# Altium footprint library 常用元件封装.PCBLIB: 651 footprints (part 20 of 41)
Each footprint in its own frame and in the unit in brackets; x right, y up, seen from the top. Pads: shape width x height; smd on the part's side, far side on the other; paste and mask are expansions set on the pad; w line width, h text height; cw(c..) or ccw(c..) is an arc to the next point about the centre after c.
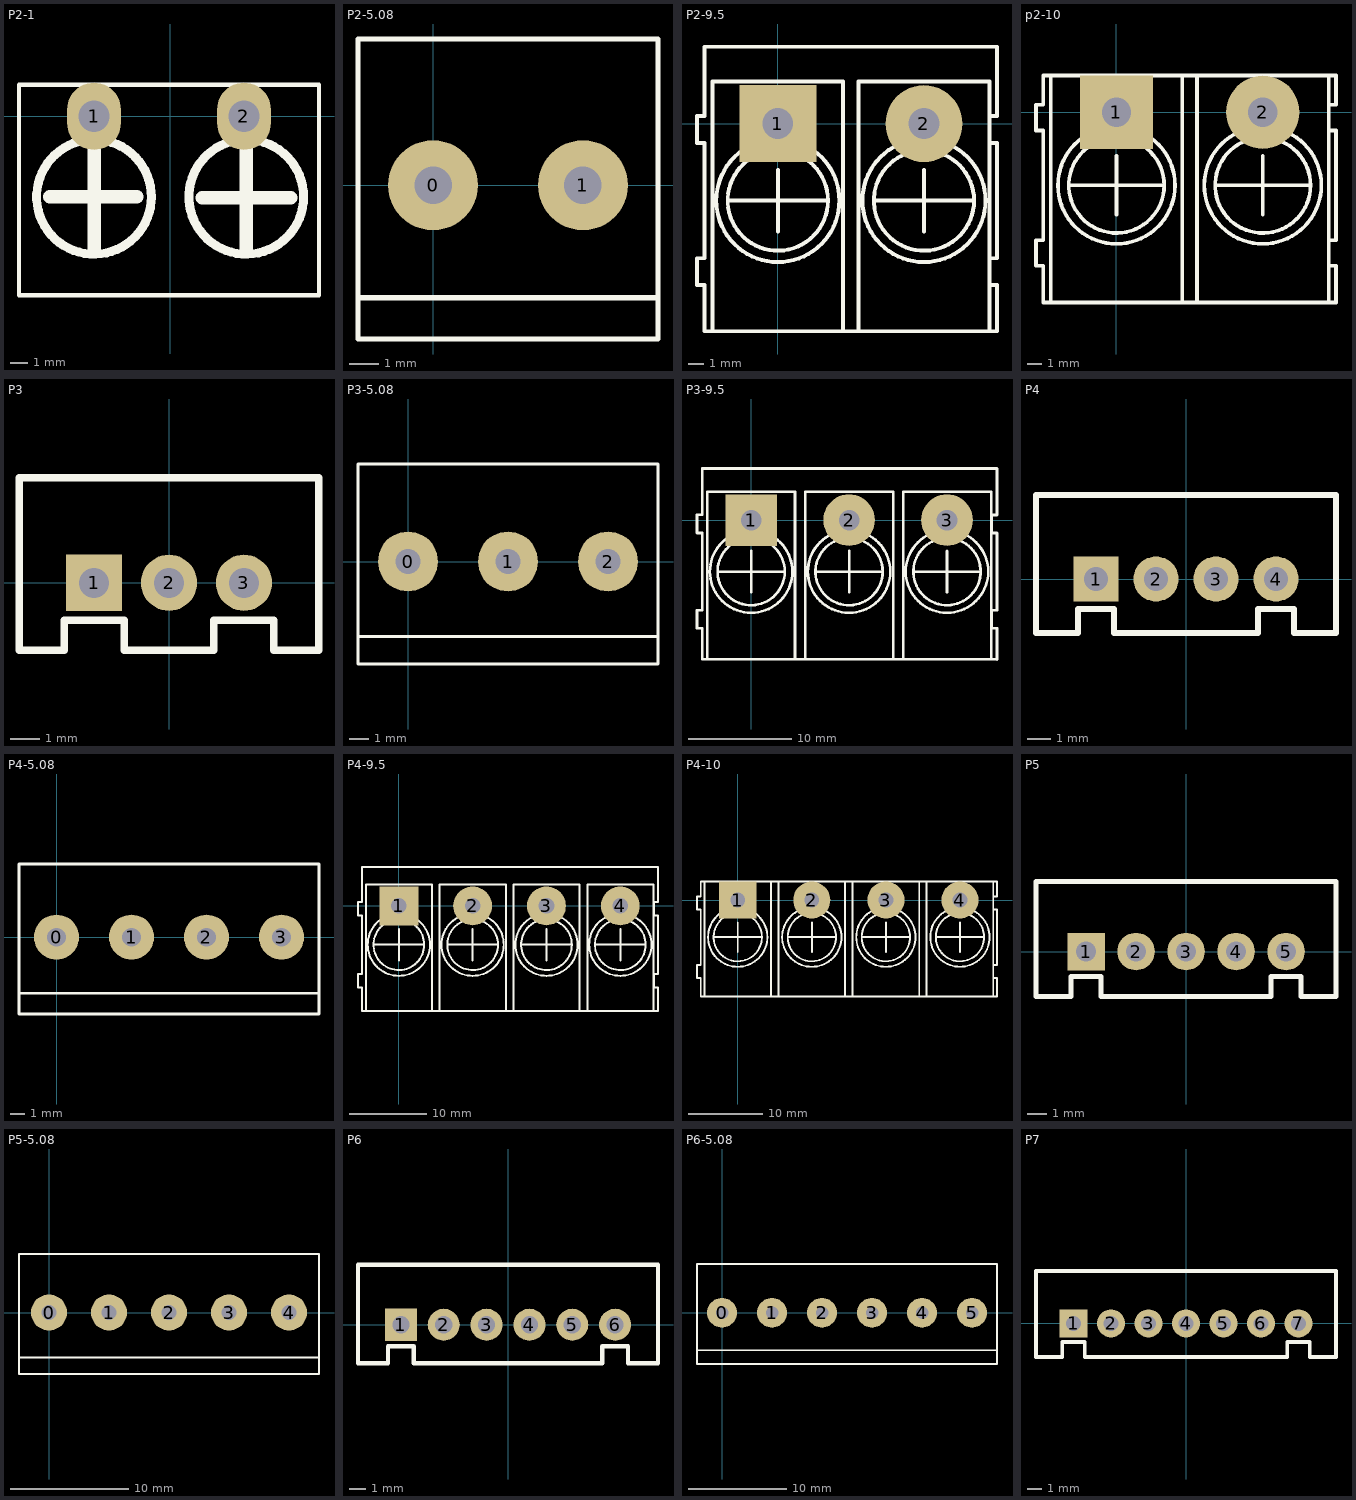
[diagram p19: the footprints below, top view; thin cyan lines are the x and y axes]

## P2-1 [mil]
pads (2):
  oval 120x150 hole 70: 1(-170,0) 2(165,0)
TopOverlay:
  circle w20: c-170,-180 r128.06
  circle w20: c170,-180 r128.06
  lines w10: 80,-89 86,-89 ; -337.5,-400 -337.5,70 332.5,70 332.5,-400 -337.5,-400
  lines w30: -269,-180 -74,-180 ; -169,-303 -169,-62 ; 72,-182 269,-182 ; 170,-301 170,-61

## P2-5.08 [mil]
height 543.31
pads (2):
  round 120 hole 50: 0(0,0) 1(200,0)
TopOverlay:
  lines w6.69: -100,-150 300,-150 ; -100,-205 -100,195 300,195 300,-205 -100,-205

## P2-9.5 [mm]
pads (2):
  rect 5x5 hole 2: 1(0,0)
  round 5 hole 2: 2(9.5,0)
TopOverlay:
  circle w0.254: c0,-5 r4
  circle w0.254: c0,-5 r3.26
  circle w0.254: c9.5,-5 r4
  circle w0.254: c9.5,-5 r3.26
  lines w0.254: -4.754,-13.5 -4.754,-10.5 -5.254,-10.5 -5.254,-8.75 -4.754,-8.75 -4.754,-1.25 -5.254,-1.25 -5.254,0.5 -4.754,0.5 -4.754,5 ; -4.75,-13.5 14.25,-13.5 ; -4.75,5 14.25,5 ; -4.25,-13.5 -4.25,2.75 4.25,2.75 4.25,-13.5 ; -3.25,-5 3.25,-5 ; 0,-7 0,-3 ; 5.25,-13.5 5.25,2.75 13.75,2.75 13.75,-13.5 ; 6.25,-5 12.75,-5 ; 9.5,-7 9.5,-3 ; 14.246,-13.5 14.246,-10.5 13.746,-10.5 13.746,-8.75 14.246,-8.75 14.246,-1.25 13.746,-1.25 13.746,0.5 14.246,0.5 14.246,5

## p2-10 [mm]
pads (2):
  rect 5x5 hole 2: 1(0,0)
  round 5 hole 2: 2(10,0)
TopOverlay:
  circle w0.254: c10,-5 r4
  circle w0.254: c10,-5 r3.26
  circle w0.254: c0,-5 r4
  circle w0.254: c0,-5 r3.26
  lines w0.254: -4.5,-13 -4.5,2.5 ; -3.25,-5 3.25,-5 ; 0,-7 0,-3 ; 4.5,-13 4.5,2.5 ; 5.5,-13 5.5,2.5 ; 6.75,-5 13.25,-5 ; 10,-7 10,-3 ; 14.5,-13 14.5,2.5 ; -5.5,-10.5 -5.5,-8.75 -5,-8.75 -5,-1.25 -5.5,-1.25 -5.5,0.5 -5,0.5 -5,2.5 15,2.5 15,0.5 14.5,0.5 14.5,-1.25 15,-1.25 15,-8.75 14.5,-8.75 14.5,-10.5 15,-10.5 15,-13 -5,-13 -5,-10.5 -5.5,-10.5

## P3 [mil]
pads (3):
  rect 75x75 hole 40: 1(-100,0)
  round 75 hole 40: 2(0,0) 3(100,0)
TopOverlay:
  lines w10: -200,-90 -140,-90 -140,-50 -60,-50 -60,-90 60,-90 60,-50 140,-50 140,-90 200,-90 200,140 -200,140 -200,-90

## P3-5.08 [mil]
height 543.31
pads (3):
  round 120 hole 50: 0(0,0) 1(200,0) 2(400,0)
TopOverlay:
  lines w6.69: -100,-150 500,-150 ; -100,-205 500,-205 500,195 -100,195 -100,-205

## P3-9.5 [mm]
pads (3):
  rect 5x5 hole 2: 1(0,0)
  round 5 hole 2: 2(9.5,0) 3(19,0)
TopOverlay:
  circle w0.254: c19,-5 r4
  circle w0.254: c19,-5 r3.26
  circle w0.254: c0,-5 r4
  circle w0.254: c0,-5 r3.26
  circle w0.254: c9.5,-5 r4
  circle w0.254: c9.5,-5 r3.26
  lines w0.254: -4.754,-13.5 -4.754,-10.5 -5.254,-10.5 -5.254,-8.75 -4.754,-8.75 -4.754,-1.25 -5.254,-1.25 -5.254,0.5 -4.754,0.5 -4.754,5 ; -4.75,-13.5 23.85,-13.525 ; -4.75,5 23.85,5 ; -4.25,-13.5 -4.25,2.75 4.25,2.75 4.25,-13.5 ; -3.25,-5 3.25,-5 ; 0,-7 0,-3 ; 5.25,-13.5 5.25,2.75 13.75,2.75 ; 6.25,-5 12.75,-5 ; 9.5,-7 9.5,-3 ; 13.775,-13.5 13.775,2.75 ; 14.75,-13.5 14.75,2.75 23.25,2.75 ; 15.75,-5 22.25,-5 ; 19,-7 19,-3 ; 23.275,-13.5 23.275,2.75 ; 23.846,-13.51 23.846,-10.51 23.346,-10.51 23.346,-8.76 23.846,-8.76 23.846,-1.26 23.346,-1.26 23.346,0.49 23.846,0.49 23.846,4.99

## P4 [mil]
pads (4):
  rect 75x75 hole 40: 1(-150,0)
  round 75 hole 40: 2(-50,0) 3(50,0) 4(150,0)
TopOverlay:
  lines w10: -250,-90 -250,0 -250,140 250,140 250,-90 180,-90 180,-50 120,-50 120,-90 -50,-90 -120,-90 -120,-50 -180,-50 -180,-90 -250,-90

## P4-5.08 [mil]
height 543.31
pads (4):
  round 120 hole 50: 0(0,0) 1(200,0) 2(400,0) 3(600,0)
TopOverlay:
  lines w6.69: -100,-150 700,-150 ; -100,-205 -100,195 700,195 700,-205 -100,-205

## P4-9.5 [mm]
pads (4):
  rect 5x5 hole 2: 1(0,0)
  round 5 hole 2: 2(9.5,0) 3(19,0) 4(28.5,0)
TopOverlay:
  circle w0.254: c28.5,-5 r4
  circle w0.254: c28.5,-5 r3.26
  circle w0.254: c0,-5 r4
  circle w0.254: c0,-5 r3.26
  circle w0.254: c9.5,-5 r4
  circle w0.254: c9.5,-5 r3.26
  circle w0.254: c19,-5 r4
  circle w0.254: c19,-5 r3.26
  lines w0.254: -4.754,-13.5 -4.754,-10.5 -5.254,-10.5 -5.254,-8.75 -4.754,-8.75 -4.754,-1.25 -5.254,-1.25 -5.254,0.5 -4.754,0.5 -4.754,5 ; -4.75,-13.5 33.35,-13.525 ; -4.75,5 33.35,4.975 ; -4.25,-13.5 -4.25,2.75 4.25,2.75 4.25,-13.5 ; -3.25,-5 3.25,-5 ; 0,-7 0,-3 ; 5.25,-13.5 5.25,2.75 13.75,2.75 ; 6.25,-5 12.75,-5 ; 9.5,-7 9.5,-3 ; 13.775,-13.5 13.775,2.75 ; 14.75,-13.5 14.75,2.75 23.25,2.75 ; 15.75,-5 22.25,-5 ; 19,-7 19,-3 ; 23.275,-13.5 23.275,2.75 ; 24.25,-13.5 24.25,2.75 32.75,2.75 ; 25.25,-5 31.75,-5 ; 28.5,-7 28.5,-3 ; 32.775,-13.5 32.775,2.75 ; 33.346,-13.51 33.346,-10.51 32.846,-10.51 32.846,-8.76 33.346,-8.76 33.346,-1.26 32.846,-1.26 32.846,0.49 33.346,0.49 33.346,4.99

## P4-10 [mm]
pads (4):
  rect 5x5 hole 2: 1(0,0)
  round 5 hole 2: 2(10,0) 3(20,0) 4(30,0)
TopOverlay:
  circle w0.254: c0,-5 r3.26
  circle w0.254: c0,-5 r4
  circle w0.254: c10,-5 r3.26
  circle w0.254: c10,-5 r4
  circle w0.254: c20,-5 r3.26
  circle w0.254: c20,-5 r4
  circle w0.254: c30,-5 r3.26
  circle w0.254: c30,-5 r4
  lines w0.254: -4.5,-13 -4.5,2.5 ; -3.25,-5 3.25,-5 ; 0,-7 0,-3 ; 4.5,-13 4.5,2.5 ; 5.5,-13 5.5,2.5 ; 6.75,-5 13.25,-5 ; 10,-7 10,-3 ; 14.5,-13 14.5,2.5 ; 15.5,-13 15.5,2.5 ; 16.75,-5 23.25,-5 ; 20,-7 20,-3 ; 24.5,-13 24.5,2.5 ; 25.5,-13 25.5,2.5 ; 26.75,-5 33.25,-5 ; 30,-7 30,-3 ; 34.5,-13 34.5,2.5 ; -5.5,-10.5 -5,-10.5 -5,-13 35,-13 35,-10.5 34.5,-10.5 34.5,-8.75 35,-8.75 35,-1.25 34.5,-1.25 34.5,0.5 35,0.5 35,2.5 -5,2.5 -5,0.5 -5.5,0.5 -5.5,-1.25 -5,-1.25 -5,-8.75 -5.5,-8.75 -5.5,-10.5

## P5 [mil]
pads (5):
  rect 75x75 hole 40: 1(-200,0)
  round 75 hole 40: 2(-100,0) 3(0,0) 4(100,0) 5(200,0)
TopOverlay:
  lines w10: -300,-90 -230,-90 -230,-50 -170,-50 -170,-90 170,-90 170,-50 230,-50 230,-90 300,-90 300,140 290,140 -300,140 -300,0 -300,-90

## P5-5.08 [mil]
height 543.31
pads (5):
  round 120 hole 50: 0(0,0) 1(200,0) 2(400,0) 3(600,0) 4(800,0)
TopOverlay:
  lines w6.69: -100,-150 900,-150 ; -100,-205 900,-205 900,195 -100,195 -100,-205

## P6 [mil]
pads (6):
  rect 75x75 hole 40: 1(-250,0)
  round 75 hole 40: 2(-150,0) 3(-50,0) 4(50,0) 5(150,0) 6(250,0)
TopOverlay:
  lines w10: -350,-90 -280,-90 -280,-50 -220,-50 -220,-90 220,-90 220,-50 280,-50 280,-90 350,-90 350,140 -350,140 -350,0 -350,-90

## P6-5.08 [mil]
height 543.31
pads (6):
  round 120 hole 50: 0(0,0) 1(200,0) 2(400,0) 3(600,0) 4(800,0) 5(1000,0)
TopOverlay:
  lines w6.69: -100,-150 1100,-150 ; -100,-205 1100,-205 1100,195 -100,195 -100,-205

## P7 [mil]
pads (7):
  rect 75x75 hole 40: 1(-300,0)
  round 75 hole 40: 2(-200,0) 3(-100,0) 4(0,0) 5(100,0) 6(200,0) 7(300,0)
TopOverlay:
  lines w10: -400,-90 -330,-90 -330,-50 -270,-50 -270,-90 210,-90 270,-90 270,-50 330,-50 330,-90 400,-90 400,140 -400,140 -400,0 -400,-90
